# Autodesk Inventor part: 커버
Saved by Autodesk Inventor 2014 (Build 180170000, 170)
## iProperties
Created: 2024-11
Part Number: 커버
Material: 일반
Document SubType Name: Modeling
Designer: dg
Density: 1 g/cm^3
Appearance: 기본값
Author: dg
Author: jhkim
Creation Date: 2024-10-25
Sending System: Autodesk Inventor 2025
Preprocessor: ST-DEVELOPER v20
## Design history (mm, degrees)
node "커버1"
node "솔리드1"
node "기준1"
